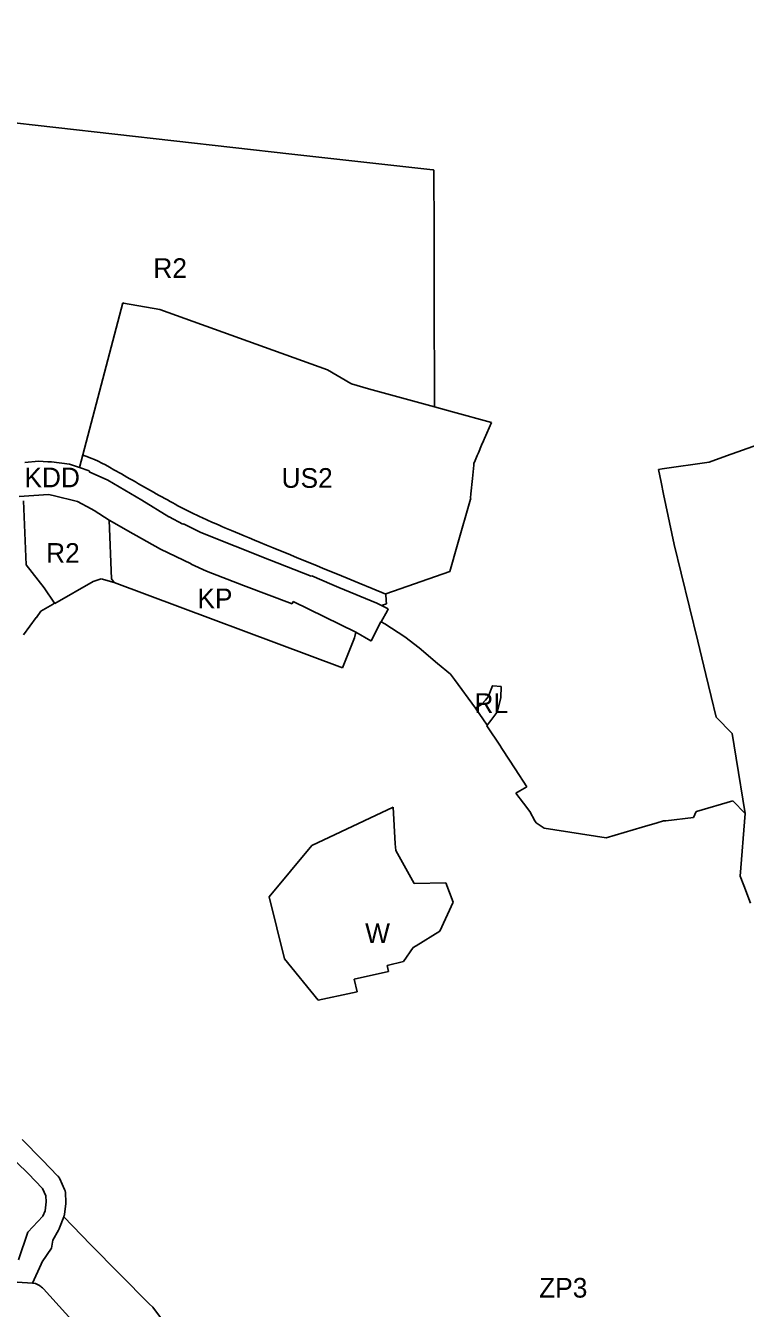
# Model space of a CAD drawing. Extents: x 7413438 to 7416393, y 5541665 to 5544118.
# Drawn here: x 7415042.1 to 7415261.6, y 5542017 to 5542408 of the extents above; entities that cross this region are included whole.
import ezdxf

# ---------------------------------------------------------------- set-up
doc = ezdxf.new("R2010")
doc.units = 0
for name, color, linetype in [('linie_rozgraniczajace', 7, 'Continuous'), ('linie_zabudowy_nieprzekraczalne', 7, 'Continuous'), ('oznaczenia_przeznaczen', 7, 'Continuous')]:
    doc.layers.add(name, color=color, linetype=linetype)

msp = doc.modelspace()

# ---------------------------------------------------------------- linework, layer by layer
at = {"layer": 'linie_rozgraniczajace'}
for p, q in [((7415018.81, 5542380.59), (7415123.31, 5542368.86)), ((7415123.31, 5542368.86), (7415166.27, 5542364.03)), ((7415166.27, 5542364.03), (7415166.29, 5542364.03)), ((7415166.29, 5542364.03), (7415166.34, 5542364.03)), ((7415166.34, 5542364.03), (7415166.58, 5542364)), ((7415166.58, 5542364), (7415166.58, 5542363.83)), ((7415166.58, 5542363.83), (7415166.58, 5542363.83)), ((7415166.58, 5542363.83), (7415166.64, 5542345.37)), ((7415166.64, 5542345.37), (7415166.7, 5542326.42)), ((7415166.7, 5542326.42), (7415166.81, 5542291.87)), ((7415058.57, 5542273.3), (7415071.75, 5542323.5)), ((7415071.75, 5542323.5), (7415071.95, 5542323.46)), ((7415071.95, 5542323.46), (7415083.03, 5542321.43)), ((7415083.03, 5542321.43), (7415134.11, 5542303.08)), ((7415134.11, 5542303.08), (7415141.32, 5542298.89)), ((7415141.32, 5542298.89), (7415141.46, 5542298.81)), ((7415141.46, 5542298.81), (7415146.67, 5542297.3)), ((7415146.67, 5542297.3), (7415166.77, 5542291.8)), ((7415166.81, 5542291.87), (7415166.77, 5542291.8)), ((7415166.77, 5542291.8), (7415172.29, 5542290.29)), ((7415172.29, 5542290.29), (7415184.14, 5542287.05)), ((7415184.14, 5542287.05), (7415182.03, 5542282.11)), ((7415181.94, 5542281.9), (7415181.72, 5542281.39)), ((7415182.03, 5542282.11), (7415181.93, 5542281.91)), ((7415181.93, 5542281.91), (7415181.94, 5542281.9)), ((7415255.86, 5542276.85), (7415272.27, 5542282.72)), ((7415181.16, 5542280.07), (7415180.17, 5542277.76)), ((7415181.72, 5542281.39), (7415181.16, 5542280.07)), ((7415041.86, 5542274.87), (7415045.99, 5542275.2)), ((7415045.99, 5542275.2), (7415048.9, 5542275.08)), ((7415048.9, 5542275.08), (7415050.05, 5542275.04)), ((7415050.05, 5542275.04), (7415055.47, 5542274.33)), ((7415055.47, 5542274.33), (7415058.57, 5542273.3)), ((7415178.74, 5542274.06), (7415178.35, 5542269.98)), ((7415178.75, 5542274.17), (7415178.74, 5542274.06)), ((7415178.78, 5542274.52), (7415178.75, 5542274.17)), ((7415179.16, 5542275.41), (7415178.78, 5542274.52)), ((7415179.19, 5542275.48), (7415179.16, 5542275.41)), ((7415179.83, 5542276.98), (7415179.19, 5542275.48)), ((7415180.17, 5542277.76), (7415179.83, 5542276.98)), ((7415236.16, 5542272.88), (7415250.54, 5542274.96)), ((7415250.54, 5542274.96), (7415255.86, 5542276.85)), ((7415061.51, 5542272.33), (7415058.57, 5542273.3)), ((7415061.49, 5542271.99), (7415061.56, 5542272.3)), ((7415067.15, 5542269.41), (7415061.49, 5542271.99)), ((7415061.56, 5542272.3), (7415061.51, 5542272.33)), ((7415235.05, 5542272.73), (7415236.16, 5542272.88)), ((7415235.87, 5542268.85), (7415235.05, 5542272.73)), ((7415077.58, 5542263.31), (7415067.15, 5542269.41)), ((7415178.35, 5542269.98), (7415177.91, 5542265.27)), ((7415236.64, 5542265.22), (7415235.87, 5542268.85)), ((7415040.14, 5542264.49), (7415049.13, 5542265.08)), ((7415042.27, 5542243.65), (7415041.48, 5542263.15)), ((7415049.13, 5542265.08), (7415050.52, 5542264.75)), ((7415050.52, 5542264.75), (7415057.96, 5542262.97)), ((7415057.96, 5542262.97), (7415062.14, 5542260.67)), ((7415085.82, 5542258.31), (7415077.58, 5542263.31)), ((7415177.76, 5542263.62), (7415173.82, 5542249.81)), ((7415177.82, 5542263.68), (7415177.76, 5542263.62)), ((7415177.91, 5542265.27), (7415177.79, 5542264.02)), ((7415177.79, 5542264.02), (7415177.82, 5542263.68)), ((7415239.9, 5542249.88), (7415236.64, 5542265.22)), ((7415062.14, 5542260.67), (7415062.98, 5542260.15)), ((7415062.98, 5542260.15), (7415067.55, 5542257.29)), ((7415085.87, 5542258.28), (7415085.82, 5542258.31)), ((7415090.08, 5542256.07), (7415085.87, 5542258.28)), ((7415067.55, 5542257.29), (7415068.33, 5542239.37)), ((7415068.47, 5542256.71), (7415067.55, 5542257.29)), ((7415073.25, 5542254.01), (7415068.47, 5542256.71)), ((7415090.24, 5542256.1), (7415090.08, 5542256.07)), ((7415095.52, 5542253.47), (7415090.24, 5542256.1)), ((7415083.19, 5542248.4), (7415073.25, 5542254.01)), ((7415116.52, 5542245.15), (7415095.52, 5542253.47)), ((7415092.56, 5542243.89), (7415083.19, 5542248.4)), ((7415173.82, 5542249.81), (7415171.48, 5542241.62)), ((7415241.97, 5542241.13), (7415239.9, 5542249.88)), ((7415047.77, 5542236.62), (7415042.27, 5542243.65)), ((7415092.56, 5542243.84), (7415092.56, 5542243.89)), ((7415097.27, 5542241.72), (7415092.56, 5542243.84)), ((7415129.17, 5542240.16), (7415116.52, 5542245.15)), ((7415065.13, 5542239.4), (7415062.73, 5542238.6)), ((7415069.1, 5542238.21), (7415065.13, 5542239.4)), ((7415068.33, 5542239.37), (7415069.1, 5542238.21)), ((7415108.53, 5542237.3), (7415097.27, 5542241.72)), ((7415129.39, 5542240.32), (7415129.17, 5542240.16)), ((7415135.48, 5542237.67), (7415129.39, 5542240.32)), ((7415171.48, 5542241.62), (7415151.94, 5542234.76)), ((7415247.04, 5542220.32), (7415241.97, 5542241.13)), ((7415050.96, 5542231.98), (7415047.77, 5542236.62)), ((7415062.73, 5542238.6), (7415050.99, 5542231.89)), ((7415138.7, 5542212.24), (7415069.1, 5542238.21)), ((7415123.39, 5542231.71), (7415108.53, 5542237.3)), ((7415135.5, 5542237.66), (7415135.48, 5542237.67)), ((7415135.53, 5542237.65), (7415135.5, 5542237.66)), ((7415137.64, 5542236.74), (7415135.53, 5542237.65)), ((7415149.19, 5542231.95), (7415137.64, 5542236.74)), ((7415050.33, 5542231.51), (7415046.79, 5542229.49)), ((7415050.88, 5542231.92), (7415050.33, 5542231.51)), ((7415050.88, 5542231.92), (7415050.96, 5542231.98)), ((7415050.99, 5542231.89), (7415050.88, 5542231.92)), ((7415123.72, 5542232.46), (7415123.39, 5542231.71)), ((7415142.82, 5542223.12), (7415123.72, 5542232.46)), ((7415149.23, 5542231.92), (7415149.19, 5542231.95)), ((7415150.65, 5542231.21), (7415149.23, 5542231.92)), ((7415152.16, 5542231.77), (7415150.65, 5542231.21)), ((7415150.65, 5542231.21), (7415152.65, 5542230.19)), ((7415151.94, 5542234.76), (7415152.09, 5542232.7)), ((7415152.09, 5542232.7), (7415152.16, 5542231.77)), ((7415045.36, 5542227.54), (7415041.49, 5542222.25)), ((7415045.42, 5542227.62), (7415045.36, 5542227.56)), ((7415045.36, 5542227.56), (7415045.36, 5542227.54)), ((7415046.79, 5542229.49), (7415045.42, 5542227.62)), ((7415152.45, 5542229.69), (7415150.48, 5542226.29)), ((7415152.65, 5542230.19), (7415152.45, 5542229.69)), ((7415142.83, 5542223.11), (7415142.39, 5542221.34)), ((7415142.83, 5542223.11), (7415142.82, 5542223.12)), ((7415147.42, 5542220.47), (7415142.83, 5542223.11)), ((7415150.45, 5542226.3), (7415147.47, 5542220.44)), ((7415150.48, 5542226.29), (7415150.45, 5542226.3)), ((7415150.48, 5542226.29), (7415151.64, 5542225.61)), ((7415151.64, 5542225.61), (7415157.75, 5542221.73)), ((7415142.39, 5542221.34), (7415138.7, 5542212.24)), ((7415147.47, 5542220.44), (7415147.42, 5542220.47)), ((7415157.75, 5542221.73), (7415162.15, 5542218.34)), ((7415249.52, 5542210.17), (7415247.04, 5542220.32)), ((7415162.15, 5542218.34), (7415167.71, 5542213.6)), ((7415167.71, 5542213.6), (7415171.64, 5542210.35)), ((7415171.64, 5542210.35), (7415172.85, 5542208.7)), ((7415172.85, 5542208.7), (7415179.27, 5542199.91)), ((7415251.15, 5542203.47), (7415249.52, 5542210.17)), ((7415183.17, 5542203.34), (7415184.48, 5542206.77)), ((7415184.48, 5542206.77), (7415184.55, 5542206.81)), ((7415184.55, 5542206.81), (7415184.56, 5542206.77)), ((7415184.56, 5542206.77), (7415187.13, 5542206.58)), ((7415187.13, 5542206.58), (7415186.98, 5542203.2)), ((7415179.27, 5542199.91), (7415179.3, 5542199.92)), ((7415179.3, 5542199.92), (7415181.1, 5542201.03)), ((7415179.3, 5542199.92), (7415182.89, 5542194.71)), ((7415181.1, 5542201.03), (7415182.34, 5542202.41)), ((7415182.34, 5542202.41), (7415183.17, 5542203.34)), ((7415186.98, 5542203.2), (7415186, 5542199.04)), ((7415252.67, 5542197.23), (7415251.15, 5542203.47)), ((7415183.99, 5542196.13), (7415182.89, 5542194.71)), ((7415185.75, 5542198.66), (7415183.99, 5542196.13)), ((7415185.88, 5542198.86), (7415185.75, 5542198.66)), ((7415186, 5542199.04), (7415185.88, 5542198.86)), ((7415257.6, 5542192.19), (7415252.67, 5542197.23)), ((7415182.89, 5542194.71), (7415182.79, 5542194.58)), ((7415182.79, 5542194.58), (7415186.9, 5542188.31)), ((7415258.82, 5542184.66), (7415257.6, 5542192.19)), ((7415186.9, 5542188.31), (7415186.99, 5542188.17)), ((7415186.99, 5542188.17), (7415187.32, 5542187.66)), ((7415187.32, 5542187.66), (7415187.54, 5542187.33)), ((7415187.54, 5542187.33), (7415191.42, 5542181.4)), ((7415261.55, 5542167.83), (7415258.82, 5542184.66)), ((7415191.42, 5542181.4), (7415194.97, 5542175.96)), ((7415192.81, 5542174.69), (7415191.62, 5542173.99)), ((7415191.62, 5542173.99), (7415193.9, 5542170.99)), ((7415194.97, 5542175.96), (7415192.81, 5542174.69)), ((7415129.38, 5542158.11), (7415154.18, 5542169.71)), ((7415154.18, 5542169.71), (7415154.83, 5542158.61)), ((7415193.9, 5542170.99), (7415195.82, 5542168.46)), ((7415195.82, 5542168.46), (7415197.37, 5542165.63)), ((7415245.71, 5542166.59), (7415246.55, 5542168.44)), ((7415246.55, 5542168.44), (7415246.65, 5542168.47)), ((7415246.65, 5542168.47), (7415257.8, 5542171.72)), ((7415257.8, 5542171.72), (7415261.55, 5542167.83)), ((7415197.37, 5542165.63), (7415197.74, 5542164.94)), ((7415197.74, 5542164.94), (7415200.26, 5542163.38)), ((7415230.13, 5542163.66), (7415234.7, 5542164.99)), ((7415234.7, 5542164.99), (7415234.7, 5542165)), ((7415234.7, 5542165), (7415234.72, 5542165)), ((7415234.72, 5542165), (7415236.59, 5542165.54)), ((7415236.59, 5542165.54), (7415237.31, 5542165.63)), ((7415237.31, 5542165.63), (7415245.71, 5542166.59)), ((7415260.04, 5542148.67), (7415261.55, 5542167.83)), ((7415200.26, 5542163.38), (7415219.14, 5542160.45)), ((7415219.14, 5542160.45), (7415230.13, 5542163.66)), ((7415116.38, 5542142.42), (7415129.38, 5542158.11)), ((7415154.83, 5542158.61), (7415154.95, 5542156.56)), ((7415154.95, 5542156.56), (7415160.62, 5542146.5)), ((7415160.62, 5542146.5), (7415170.29, 5542146.72)), ((7415170.29, 5542146.72), (7415172.5, 5542140.8)), ((7415261.1, 5542145.86), (7415260.04, 5542148.67)), ((7415263.13, 5542140.48), (7415261.1, 5542145.86)), ((7415121.08, 5542123.52), (7415116.38, 5542142.42)), ((7415172.5, 5542140.8), (7415168.37, 5542131.95)), ((7415168.37, 5542131.95), (7415161.17, 5542127.51)), ((7415160.33, 5542126.98), (7415157.3, 5542122.67)), ((7415161.17, 5542127.51), (7415160.33, 5542126.98)), ((7415131.31, 5542110.88), (7415121.08, 5542123.52)), ((7415157.3, 5542122.67), (7415152.36, 5542121.44)), ((7415152.36, 5542121.44), (7415152.8, 5542119.7)), ((7415152.8, 5542119.7), (7415142.32, 5542117.31)), ((7415142.32, 5542117.31), (7415143.17, 5542113.44)), ((7415141.76, 5542113.14), (7415131.31, 5542110.88)), ((7415143.17, 5542113.44), (7415141.76, 5542113.14)), ((7415041.01, 5542068.47), (7415047.13, 5542062.22)), ((7415042.84, 5542058.02), (7415039.47, 5542061.47)), ((7415047.13, 5542062.22), (7415051.96, 5542057.28)), ((7415047.3, 5542053.46), (7415042.84, 5542058.02)), ((7415051.96, 5542057.28), (7415051.99, 5542057.25)), ((7415051.99, 5542057.25), (7415052.12, 5542057.1)), ((7415052.12, 5542057.1), (7415052.24, 5542056.94)), ((7415052.24, 5542056.94), (7415052.35, 5542056.78)), ((7415052.35, 5542056.78), (7415052.45, 5542056.61)), ((7415052.45, 5542056.61), (7415052.54, 5542056.44)), ((7415052.54, 5542056.44), (7415052.56, 5542056.4)), ((7415052.56, 5542056.4), (7415054.01, 5542053.15)), ((7415048.3, 5542051.23), (7415047.3, 5542053.46)), ((7415048.37, 5542049.4), (7415048.3, 5542051.23)), ((7415054.01, 5542053.15), (7415054.07, 5542053.01)), ((7415054.07, 5542053.01), (7415054.14, 5542052.82)), ((7415054.14, 5542052.82), (7415054.19, 5542052.63)), ((7415054.19, 5542052.63), (7415054.23, 5542052.44)), ((7415054.23, 5542052.44), (7415054.26, 5542052.24)), ((7415054.26, 5542052.24), (7415054.27, 5542052.05)), ((7415054.27, 5542052.05), (7415054.38, 5542049.4)), ((7415048.05, 5542046.7), (7415048.37, 5542049.4)), ((7415054.36, 5542048.93), (7415053.97, 5542045.6)), ((7415054.37, 5542049.01), (7415054.36, 5542048.93)), ((7415054.38, 5542049.21), (7415054.37, 5542049.01)), ((7415054.38, 5542049.4), (7415054.38, 5542049.21)), ((7415042.78, 5542040.21), (7415047.39, 5542045.01)), ((7415047.39, 5542045.01), (7415048.05, 5542046.7)), ((7415052.46, 5542041.54), (7415053.78, 5542044.85)), ((7415053.8, 5542044.92), (7415053.78, 5542044.85)), ((7415053.78, 5542044.85), (7415061.9, 5542036.43)), ((7415053.87, 5542045.11), (7415053.8, 5542044.92)), ((7415053.91, 5542045.3), (7415053.87, 5542045.11)), ((7415053.95, 5542045.49), (7415053.91, 5542045.3)), ((7415053.97, 5542045.6), (7415053.95, 5542045.49)), ((7415039.94, 5542031.78), (7415042.78, 5542040.21)), ((7415050.39, 5542037.76), (7415052.15, 5542040.83)), ((7415052.15, 5542040.83), (7415052.2, 5542040.93)), ((7415052.2, 5542040.93), (7415052.29, 5542041.11)), ((7415052.29, 5542041.11), (7415052.33, 5542041.22)), ((7415052.33, 5542041.22), (7415052.46, 5542041.54)), ((7415049.98, 5542035.29), (7415050.39, 5542037.76)), ((7415061.9, 5542036.43), (7415079.8, 5542018.38)), ((7415047.15, 5542031.12), (7415049.98, 5542035.29)), ((7415044.22, 5542024.64), (7415046.84, 5542030.45)), ((7415046.84, 5542030.45), (7415047.15, 5542031.12)), ((7415044.22, 5542024.64), (7415032.01, 5542025.42)), ((7415045.13, 5542024.58), (7415044.22, 5542024.64)), ((7415046.31, 5542023.91), (7415045.13, 5542024.58)), ((7415046.46, 5542023.83), (7415046.31, 5542023.91)), ((7415046.73, 5542023.65), (7415046.46, 5542023.83)), ((7415046.99, 5542023.45), (7415046.73, 5542023.65)), ((7415047.24, 5542023.23), (7415046.99, 5542023.45)), ((7415047.47, 5542023.01), (7415047.24, 5542023.23)), ((7415047.56, 5542022.91), (7415047.47, 5542023.01)), ((7415059, 5542010.24), (7415047.56, 5542022.91)), ((7415079.8, 5542018.38), (7415080.87, 5542017.3)), ((7415080.87, 5542017.3), (7415093.21, 5542000.9))]:
    msp.add_line(p, q, dxfattribs=at)
at = {"layer": 'linie_zabudowy_nieprzekraczalne'}
for points in [[(7415354.02, 5542157.54), (7415351.12, 5542172.84), (7415343.57, 5542209.73), (7415339.4, 5542229.81), (7415336.1, 5542245.87), (7415329.78, 5542276.17), (7415325.62, 5542295.99), (7415324.08, 5542302.96), (7415325.54, 5542310.25), (7415322.96, 5542316.74), (7415320.29, 5542324.11), (7415316.96, 5542335.38), (7415310.62, 5542361.08), (7415303.17, 5542393.62), (7415293.51, 5542434.1), (7415288.48, 5542454.95), (7415286.07, 5542465.01), (7415283.42, 5542473.12), (7415276.7, 5542491.46), (7415272.35, 5542501.51), (7415261.71, 5542522.05), (7415253.51, 5542538.9), (7415250.76, 5542540.28)], [(7415059.53, 5542277.04), (7415063.1, 5542275.94), (7415067.46, 5542273.61), (7415083.6, 5542264.28), (7415095.07, 5542258.1), (7415106.51, 5542253.36), (7415151.91, 5542234.72)]]:
    msp.add_open_spline(points, degree=3, dxfattribs=at)

# ---------------------------------------------------------------- texts
at = {"layer": 'oznaczenia_przeznaczen'}
for s, p in [('R2', (7415081.05, 5542331.1)), ('KDD', (7415041.74, 5542267.28)), ('US2', (7415120.15, 5542267.12)), ('R2', (7415048.36, 5542244.25)), ('KP', (7415094.48, 5542230.41)), ('RL', (7415178.97, 5542198.45)), ('W', (7415145.64, 5542128.31)), ('ZP3', (7415198.69, 5542020.23))]:
    msp.add_text(s, height=6, dxfattribs=at).set_placement(p)

doc.saveas('drawing.dxf')
